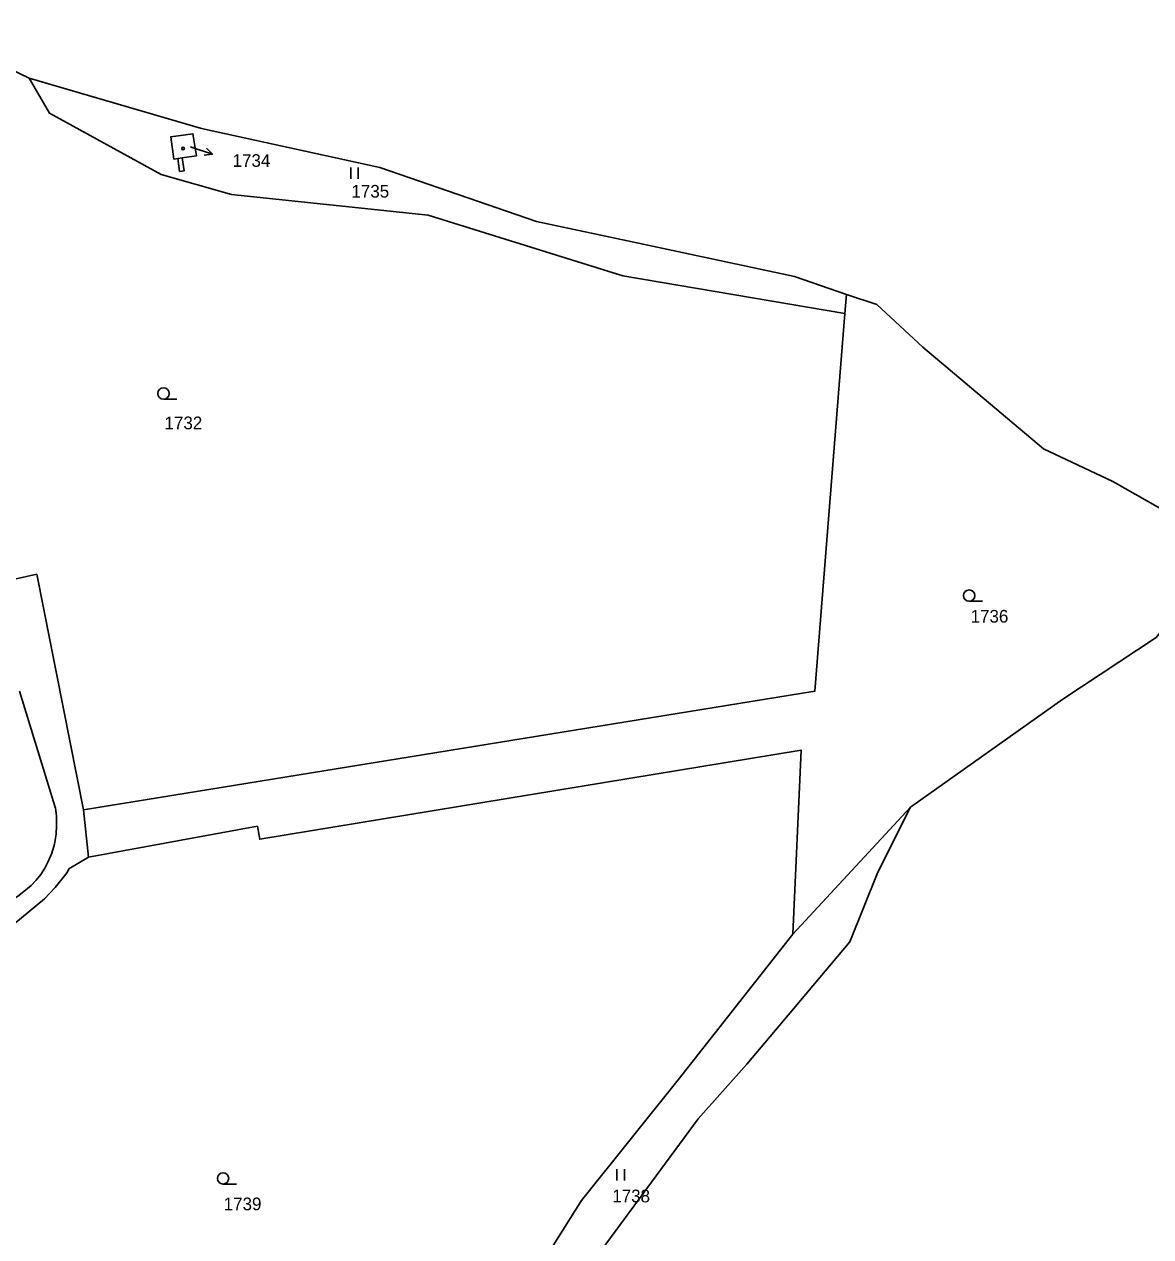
# Model space of a CAD drawing. Extents: x -737240 to -735272, y -1119606 to -1117878.
# Drawn here: x -735622.3 to -735471.5, y -1118521 to -1118358.6 of the extents above; entities that cross this region are included whole.
import ezdxf

# ---------------------------------------------------------------- set-up
doc = ezdxf.new("R2010")
doc.units = 0
for name, color, linetype in [('Level 1', 7, 'Continuous'), ('Level 16', 7, 'Continuous'), ('Level 18', 7, 'Continuous'), ('Level 19', 7, 'Continuous'), ('Level 25', 7, 'Continuous'), ('Level 4', 7, 'Continuous')]:
    doc.layers.add(name, color=color, linetype=linetype)

msp = doc.modelspace()

# ---------------------------------------------------------------- linework, layer by layer
at = {"layer": 'Level 1'}
for p, q in [((-735636.37, -1118358.63), (-735621.63, -1118365.87)), ((-735512.21, -1118394.81), (-735512.4, -1118397.35)), ((-735613.65, -1118470.16), (-735614.32, -1118463.85)), ((-735503.61, -1118463.49), (-735519.37, -1118480.51))]:
    msp.add_line(p, q, dxfattribs=at)
for points in [[(-735621.63, -1118365.87), (-735618.9, -1118370.55), (-735603.94, -1118378.77), (-735594.52, -1118381.43), (-735568.2, -1118384.22), (-735542.14, -1118392.32), (-735512.4, -1118397.35)], [(-735621.63, -1118365.87), (-735598.54, -1118372.61), (-735574.67, -1118377.81), (-735553.69, -1118385.05), (-735539.42, -1118388.1), (-735519.15, -1118392.41), (-735512.21, -1118394.81)], [(-735601.72, -1118376.63), (-735602.22, -1118376.7), (-735602.66, -1118373.69), (-735599.68, -1118373.3), (-735599.21, -1118376.26), (-735601.12, -1118376.54)], [(-735601.12, -1118376.54), (-735600.86, -1118378.26), (-735601.47, -1118378.35), (-735601.72, -1118376.63)], [(-735512.21, -1118394.81), (-735508.12, -1118396.15), (-735501.99, -1118401.88), (-735485.81, -1118415.51), (-735476.52, -1118419.89), (-735464.25, -1118426.82), (-735463.73, -1118431.87), (-735470.75, -1118440.77), (-735483.25, -1118449), (-735503.61, -1118463.49)], [(-735512.4, -1118397.35), (-735516.45, -1118447.96), (-735614.32, -1118463.85)], [(-735614.32, -1118463.85), (-735620.6, -1118432.3), (-735624.75, -1118433.2)], [(-735622.9, -1118447.96), (-735618.33, -1118462.78), (-735618.1, -1118463.6), (-735617.96, -1118464.66), (-735617.93, -1118465.9), (-735617.98, -1118467.11), (-735618.21, -1118468.43), (-735618.57, -1118469.64), (-735619.03, -1118470.68), (-735619.51, -1118471.64), (-735620.06, -1118472.49), (-735620.65, -1118473.25), (-735621.36, -1118473.98), (-735622.33, -1118474.8), (-735623.16, -1118475.44), (-735623.98, -1118475.91), (-735644.51, -1118479.65)], [(-735519.37, -1118480.51), (-735518.27, -1118455.85), (-735590.75, -1118467.78), (-735591.05, -1118466.05), (-735613.65, -1118470.16)], [(-735503.61, -1118463.49), (-735508.01, -1118472.18), (-735511.73, -1118481.53), (-735519.3, -1118490.51), (-735525.54, -1118497.92), (-735532.04, -1118505.22), (-735546.3, -1118524.58), (-735554.58, -1118536.89), (-735555.79, -1118541.74), (-735553.06, -1118556.51), (-735550.81, -1118560.64), (-735548.38, -1118563.95), (-735546.55, -1118569.39)], [(-735613.65, -1118470.16), (-735616.32, -1118471.76), (-735616.53, -1118472.22), (-735618.11, -1118474.23), (-735619.57, -1118475.78), (-735623.64, -1118479.17), (-735662.83, -1118487.49), (-735667.92, -1118488.58)], [(-735559.18, -1118566.96), (-735562.31, -1118550.25), (-735560.69, -1118536.88), (-735547.65, -1118516.15), (-735534.72, -1118500), (-735519.37, -1118480.51)]]:
    msp.add_lwpolyline(points, dxfattribs=at)
at = {"layer": 'Level 16'}
for points in [[(-735600.02, -1118375.04), (-735599.92, -1118375.07), (-735597.077, -1118376.027)], [(-735597.865, -1118375.234), (-735597.077, -1118376.027), (-735598.184, -1118376.182)]]:
    msp.add_lwpolyline(points, dxfattribs=at)
at = {"layer": 'Level 25'}
for p, q in [((-735578.567, -1118377.835), (-735578.567, -1118379.335)), ((-735577.545, -1118379.335), (-735577.545, -1118377.835)), ((-735601.838, -1118408.84), (-735603.62, -1118408.84)), ((-735493.988, -1118435.9), (-735495.77, -1118435.9)), ((-735542.927, -1118511.965), (-735542.927, -1118513.465)), ((-735541.905, -1118513.465), (-735541.905, -1118511.965)), ((-735593.868, -1118513.96), (-735595.65, -1118513.96))]:
    msp.add_line(p, q, dxfattribs=at)
for centre, major_axis, ratio in [((-735601.01, -1118375.27), (0.18, 0), 0.9848078), ((-735603.62, -1118408.084), (0.764, 0), 0.9894236), ((-735495.77, -1118435.144), (0.764, 0), 0.9894236), ((-735595.65, -1118513.204), (0.764, 0), 0.9894236)]:
    msp.add_ellipse(centre, major_axis=major_axis, ratio=ratio, dxfattribs=at)
at = {"layer": 'Level 4'}
msp.add_line((-735601.72, -1118376.63), (-735601.12, -1118376.54), dxfattribs=at)

# ---------------------------------------------------------------- texts
at = {"layer": 'Level 16'}
msp.add_text('1734', height=1.7, dxfattribs=at).set_placement((-735594.38, -1118377.73))
at = {"layer": 'Level 18'}
for s, p in [('1735', (-735578.47, -1118381.85)), ('1732', (-735603.49, -1118412.87)), ('1736', (-735495.58, -1118438.77)), ('1739', (-735595.57, -1118517.47)), ('1738', (-735543.55, -1118516.41))]:
    msp.add_text(s, height=1.7, dxfattribs=at).set_placement(p)
at = {"layer": 'Level 19'}
msp.add_text('1734', height=0.1, dxfattribs=at).set_placement((-735599.895, -1118375.04))

doc.saveas('drawing.dxf')
